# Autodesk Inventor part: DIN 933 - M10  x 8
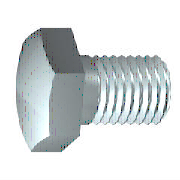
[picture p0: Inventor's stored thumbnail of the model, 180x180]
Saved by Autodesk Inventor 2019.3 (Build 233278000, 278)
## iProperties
Created: 2018-01
Part Number: DIN 933 - M10  x 8
Material: Ocel, měkká
Description: Šestihranný šroub
Document SubType Name: Modeling
Standard: DIN 933
Designer: B-hon
Standards Organization: DIN
Language: cs-CZ
Size Designation: M10  x 8
Categories: <MemberInstance><Categories><Category DisplayName="Spojovací materiál" InternalName="e4da775c-781d-43d5-af7c-5136215cf5a6" Mnemonic="FSTN"><Category DisplayName
Density: 7.85 g/cm^3
Appearance: Pololeštěná
IsCustomPart: 0
Author: B-hon
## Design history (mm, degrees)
sketch "Náčrt1"
  geometry: L1 (0, 7.7)-(0, 4.594); L2 (4.5, 5)-(8, 5); L3 (8, 5)-(8, 0); L4 (8, 0)-(-0.6, 0); L5 (-2.32, 0)-(9.72, 0) reference; L6 (-0.6, 0)-(-0.6, 7.7); L7 (-0.6, 7.7)-(0, 7.7); L8 (4.5, 5)-(3.58, 4.594); L9 (3.58, 4.594)-(0, 4.594); L10 (0, -1.54)-(0, 9.24) reference
  constraints: 16 end point, 2 collinear, 2 perpendicular, 1 parallel
  dimensions: "d0" = 8 distance between parallel lines of L3 L1 (= NLG); "d1" = 3.5 distance from line of L2.start L3 (= GEL); "d2" = 10 diameter of L2 L4 (= GD); "d9" = 0.6001 distance between parallel lines of L6 L1 (computed from SD); "d10" = 15.4 diameter of L7 L4 (= SD2); "d13" = 0.92028 horizontal distance of L2.start L8.end (computed from GAL); "d14" = 9.1881 diameter of L9 L4 (= BDM)
revolve "Těleso" sketch "Náčrt1" stored, may be unused: angle "d12" = 90 deg
sketch "Náčrt2"
  geometry: L1 (0, 9.815)-(8.5, 4.907); L2 (8.5, 4.907)-(8.5, -4.907); L3 (8.5, -4.907)-(0, -9.815); L4 (0, -9.815)-(-8.5, -4.907); L5 (-8.5, -4.907)-(-8.5, 4.907); L6 (-8.5, 4.907)-(0, 9.815); 2 further points
  constraints: 12 end point, 1 coincident, 1 vertical, 11 other
  dimensions: "d11" = 17 distance between parallel lines of L5 L2 (= SW)
extrude "Hlava" join sketch "Náčrt2" distance "d3" = 5.8 (= KOH - SD); taper "d4" = 0 deg
sketch "Náčrt4"
  geometry: L1 (-6.4, 8.5)-(-6.4, 9.815); L2 (-6.4, 9.815)-(-5.641, 9.815); L3 (-5.641, 9.815)-(-6.4, 8.5); L4 (-7.56, 0)-(0.56, 0) reference; L5 (-0.6, 9.815)-(-6.4, 9.815) reference; L6 (-6.4, 4.907)-(-6.4, 9.815) reference
  constraints: 6 end point, 2 collinear, 1 perpendicular, 1 vertical
  dimensions: "d5" = 30 deg angle of L3 L1 (= ANG1); "d19" = 17 diameter of L1.start L4 (= SW0)
revolve "Zkosení1" sketch "Náčrt4" stored, may be unused: angle "d21" = 90 deg
workplane "Work Plane1"
body "Solid1"
feature "Závit" dims "d15" = 3.5 (= GEL), "d16" = 0
chamfer "Zkosení2" distance "d6" = 0.92018 (= -0.5 x SPD + 0.5 x GD); stored, may be unused: second distance "d7" = 0.92028 (computed from GUL), angle "d55" = 45 deg
other parameters: "NLG" = 8 [user parameter; used in 1 equation term], "GD" = 10 (= NND) [user parameter; used in 2 equation terms], "BDM" = 9.1881 [user parameter; used in 1 equation term], "KOH" = 6.4 [user parameter; used in 1 equation term], "GEL" = 3.5 [user parameter; used in 2 equation terms], "SW" = 17 [user parameter; used in 2 equation terms], "SW0" = 17 [user parameter; used in 1 equation term], "SPD" = 8.15965 (= NND - 1.2269 x PTC) [user parameter; used in 1 equation term], "SD2" = 15.4 [user parameter; used in 1 equation term], "SD" = 0.6 [user parameter; used in 2 equation terms], "ANG1" = 30 deg [user parameter; used in 1 equation term], "GAL" = 0.92018 (= 0.61345 x PTC) [user parameter; used in 1 equation term], "GUL" = 0.92018 (= 0.61345 x PTC) [user parameter; used in 1 equation term], "d8" = 0, "RR" = 0.4 [user parameter], "d57" = 0, "d58" = 0, "TPU" = 6.66667 (computed from PTC) [user parameter], "GD1" = 8.15965 (= THREADDIA - 1.2269 x PTC) [user parameter], "TOA" = 30 deg [user parameter], "PTC" = 1.5 [user parameter; used in 5 equation terms], "E0" = 19.635 (= 1.155 x SW) [user parameter]
